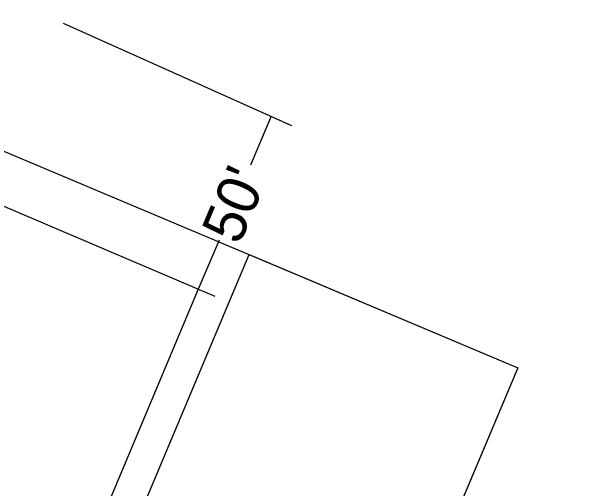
# Model space of a CAD drawing. Extents: x 14104283 to 14129344, y 8637090 to 8673339.
# Drawn here: x 14119000.1 to 14119146.8, y 8668379.3 to 8668502 of the extents above; entities that cross this region are included whole.
import ezdxf

# ---------------------------------------------------------------- set-up
doc = ezdxf.new("R2010")
doc.units = 0
for name, color, linetype in [('dsnNonPlotable', 7, 'Continuous'), ('dsnPaintExistingBrokenLaneLineWhite', 7, 'Continuous'), ('dsnPaintExistingEdgeLineRightWhite', 7, 'Continuous'), ('dsnPaintRemoveLaneLineWhite', 7, 'Continuous'), ('dsnShadingPaved', 7, 'Continuous'), ('dsnStdLabel', 7, 'Continuous'), ('dsnStgShadingPrevPav', 7, 'Continuous'), ('dsnTapePlaceChannelizingLaneWhite', 7, 'Continuous'), ('dsnTapePlaceChannelizingLaneYellow', 7, 'Continuous'), ('dsnTextOverlapEven', 7, 'Continuous')]:
    doc.layers.add(name, color=color, linetype=linetype)

msp = doc.modelspace()

# ---------------------------------------------------------------- linework, layer by layer
at = {"layer": 'dsnNonPlotable'}
msp.add_lwpolyline([(14118056.48, 8667161.91), (14118665.06, 8668606.45), (14119130.44, 8668410.38), (14118521.87, 8666965.84)], close=True, dxfattribs=at)
at = {"layer": 'dsnPaintExistingBrokenLaneLineWhite'}
msp.add_arc((14121592.11, 8667345.68), 2864.95, 147.15737, 157.1633, dxfattribs=at)
at = {"layer": 'dsnPaintExistingEdgeLineRightWhite'}
msp.add_arc((14121592.11, 8667345.68), 2852.95, 147.15737, 157.1633, dxfattribs=at)
at = {"layer": 'dsnPaintRemoveLaneLineWhite'}
msp.add_arc((14121592.11, 8667345.68), 2876.95, 153.70867, 156.90337, dxfattribs=at)
at = {"layer": 'dsnShadingPaved'}
for centre, radius, start, end in [((14121955.85, 8666791.92), 3512, 144.95493, 152.69211), ((14121955.85, 8666791.92), 3500, 144.95493, 152.69211), ((14121592.11, 8667345.68), 2888.95, 151.24538, 156.90337), ((14121592.11, 8667345.68), 2876.95, 151.24538, 156.90337)]:
    msp.add_arc(centre, radius, start, end, dxfattribs=at)
at = {"layer": 'dsnStdLabel'}
for p, q in [((14119013.41, 8668499), (14119072.14, 8668472.73)), ((14119066.93, 8668475.06), (14119061.62, 8668462.46)), ((14118993.28, 8668453.99), (14119052.46, 8668428.75)), ((14119053.52, 8668443.22), (14119048.19, 8668430.57)), ((14119048.19, 8668430.57), (14118862.01, 8667988.64))]:
    msp.add_line(p, q, dxfattribs=at)
at = {"layer": 'dsnStgShadingPrevPav'}
for radius, start in [(5512, 146.42562), (5488, 146.42119)]:
    msp.add_arc((14123732.96, 8665874.38), radius, start, 157.1633, dxfattribs=at)
at = {"layer": 'dsnTapePlaceChannelizingLaneWhite'}
msp.add_arc((14121592.11, 8667345.68), 2876.95, 151.24538, 156.90337, dxfattribs=at)
at = {"layer": 'dsnTapePlaceChannelizingLaneYellow'}
msp.add_arc((14121592.11, 8667345.68), 2888.95, 151.24538, 156.90337, dxfattribs=at)
at = {"layer": 'dsnTextOverlapEven'}
for points in [[(14119130.44, 8668410.38), (14119053.07, 8668226.74), (14118983.96, 8668255.86), (14119061.32, 8668439.5)], [(14118983.96, 8668255.86), (14119061.32, 8668439.5), (14119130.44, 8668410.38), (14119053.07, 8668226.74)]]:
    msp.add_lwpolyline(points, close=True, dxfattribs=at)

# ---------------------------------------------------------------- texts
at = {"layer": 'dsnStdLabel'}
msp.add_text("50'", height=10.8, rotation=67.1547, dxfattribs=at).set_placement((14119058.72, 8668441.66))

doc.saveas('drawing.dxf')
